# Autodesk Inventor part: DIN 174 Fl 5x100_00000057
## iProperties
Created: 2006-03
Part Number: DIN 174 Fl 5x100_00000057
Material: Default
Document SubType Name: Modeling
Designer: Carlo
Stock Number: DIN 174 Fl 5x100
Mass: 881.349 g
Surface Area: 3712.08 cm^2
Volume: 881.349 cm^3
Density: 1 g/cm^3
G_L: 1762.896 mm
G_W: 5.000 mm
G_H: 100.000 mm
AFG_Item: 100 x 5
CSToolsMass: 1.0
CSToolsVolume: 881349.0
CSToolsArea: 3712.0
Author: Carlo
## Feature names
1. AFG_Detailed_DIN 174 Fl 5x100_00000057 [Extrusion]
2. AFG_Simplified_DIN 174 Fl 5x100_00000057 [Extrusion]
3. AFG_StartExtrusion_1 [Extrusion]
4. AFG_StartExtrusion_2 [Extrusion]
5. AFG_EndExtrusion_1 [Extrusion]
6. AFG_EndExtrusion_2 [Extrusion]
